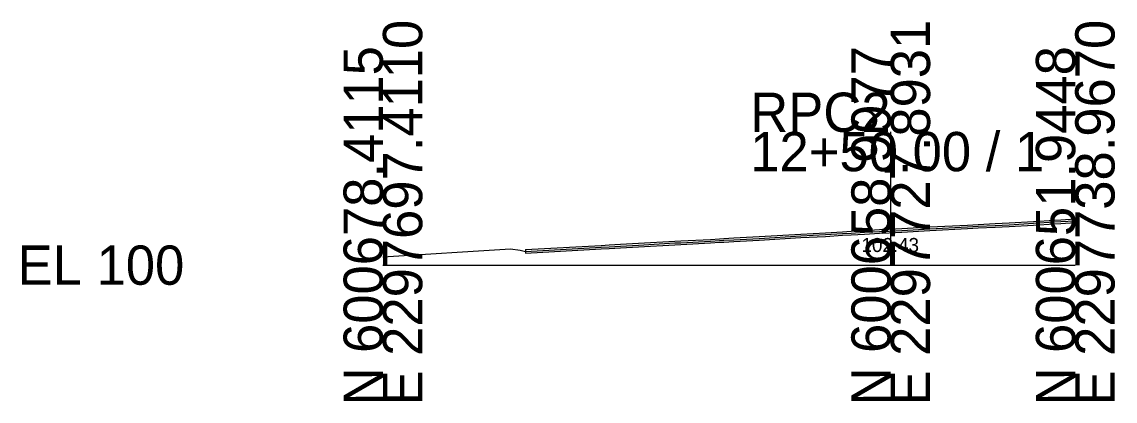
# Model space of a CAD drawing. Extents: x 2124 to 2376, y -10 to 1517.
# Drawn here: x 2124.3 to 2202.1, y 1490.3 to 1517.3 of the extents above; entities that cross this region are included whole.
import ezdxf

# ---------------------------------------------------------------- set-up
doc = ezdxf.new("R2010")
doc.units = 0
for name, color, linetype in [('Exist Cross Section Cell', 7, 'Continuous'), ('Exist XS Center Line Elevation Label', 7, 'Continuous'), ('Exist XS Ground Line', 7, 'Continuous'), ('Prop CMT Pvmt Surface', 7, 'Continuous'), ('Prop CMT Pvmt Surface Overlay', 7, 'Continuous')]:
    doc.layers.add(name, color=color, linetype=linetype)

msp = doc.modelspace()

# ---------------------------------------------------------------- linework, layer by layer
at = {"layer": 'Exist Cross Section Cell'}
for p, q in [((2186.139, 1500), (2186.139, 1509.492)), ((2150, 1500), (2186.139, 1500)), ((2186.139, 1500), (2199.269, 1500))]:
    msp.add_line(p, q, dxfattribs=at)
at = {"layer": 'Exist XS Ground Line'}
msp.add_lwpolyline([(2150, 1500.584), (2159.091, 1501.16), (2159.776, 1501.06), (2160.141, 1500.978), (2165.542, 1501.282), (2166.094, 1501.316), (2166.898, 1501.36), (2168.181, 1501.435), (2170.786, 1501.578), (2171.196, 1501.596), (2173.314, 1501.703), (2173.947, 1501.758), (2174.264, 1501.771), (2174.966, 1501.81), (2176.781, 1501.906), (2179.745, 1502.085), (2181.507, 1502.177), (2182.709, 1502.256), (2183.318, 1502.287), (2184.274, 1502.344), (2185.346, 1502.403), (2186.021, 1502.428), (2186.476, 1502.454), (2186.939, 1502.479), (2188.927, 1502.598), (2191.601, 1502.734), (2192.372, 1502.78), (2193.581, 1502.836), (2194.565, 1502.881), (2196.291, 1502.985), (2197.804, 1503.075), (2198.235, 1503.103), (2199.269, 1503.164)], dxfattribs=at)
at = {"layer": 'Prop CMT Pvmt Surface'}
msp.add_line((2160.141, 1501.103), (2160.141, 1500.853), dxfattribs=at)
for points in [[(2160.141, 1501.103), (2165.542, 1501.407), (2166.094, 1501.441), (2166.898, 1501.485), (2168.181, 1501.56), (2170.786, 1501.703), (2171.196, 1501.721), (2173.314, 1501.828), (2173.947, 1501.883), (2174.264, 1501.896), (2174.966, 1501.935), (2176.781, 1502.031), (2179.745, 1502.21), (2181.507, 1502.302), (2182.709, 1502.381), (2183.318, 1502.412), (2184.274, 1502.469), (2185.346, 1502.528), (2186.021, 1502.553), (2186.476, 1502.579), (2186.939, 1502.604), (2188.927, 1502.723), (2191.601, 1502.859), (2192.372, 1502.905), (2193.581, 1502.961), (2194.565, 1503.006), (2196.291, 1503.11), (2197.804, 1503.2), (2198.235, 1503.228), (2199.269, 1503.289)], [(2160.141, 1500.853), (2165.542, 1501.157), (2166.094, 1501.191), (2166.898, 1501.235), (2168.181, 1501.31), (2170.786, 1501.453), (2171.196, 1501.471), (2173.314, 1501.578), (2173.947, 1501.633), (2174.264, 1501.646), (2174.966, 1501.685), (2176.781, 1501.781), (2179.745, 1501.96), (2181.507, 1502.052), (2182.709, 1502.131), (2183.318, 1502.162), (2184.274, 1502.219), (2185.346, 1502.278), (2186.021, 1502.303), (2186.476, 1502.329), (2186.939, 1502.354), (2188.927, 1502.473), (2191.601, 1502.609), (2192.372, 1502.655), (2193.581, 1502.711), (2194.565, 1502.756), (2196.291, 1502.86), (2197.804, 1502.95), (2198.235, 1502.978), (2199.269, 1503.039)]]:
    msp.add_lwpolyline(points, dxfattribs=at)
at = {"layer": 'Prop CMT Pvmt Surface Overlay'}
for p, q in [((2199.269, 1503.289), (2199.269, 1503.039)), ((2160.141, 1501.103), (2160.141, 1500.853))]:
    msp.add_line(p, q, dxfattribs=at)
for points in [[(2160.141, 1501.103), (2165.542, 1501.407), (2166.094, 1501.441), (2166.898, 1501.485), (2168.181, 1501.56), (2170.786, 1501.703), (2171.196, 1501.721), (2173.314, 1501.828), (2173.947, 1501.883), (2174.264, 1501.896), (2174.966, 1501.935), (2176.781, 1502.031), (2179.745, 1502.21), (2181.507, 1502.302), (2182.709, 1502.381), (2183.318, 1502.412), (2184.274, 1502.469), (2185.346, 1502.528), (2186.021, 1502.553), (2186.476, 1502.579), (2186.939, 1502.604), (2188.927, 1502.723), (2191.601, 1502.859), (2192.372, 1502.905), (2193.581, 1502.961), (2194.565, 1503.006), (2196.291, 1503.11), (2197.804, 1503.2), (2198.235, 1503.228), (2199.269, 1503.289)], [(2160.141, 1500.853), (2165.542, 1501.157), (2166.094, 1501.191), (2166.898, 1501.235), (2168.181, 1501.31), (2170.786, 1501.453), (2171.196, 1501.471), (2173.314, 1501.578), (2173.947, 1501.633), (2174.264, 1501.646), (2174.966, 1501.685), (2176.781, 1501.781), (2179.745, 1501.96), (2181.507, 1502.052), (2182.709, 1502.131), (2183.318, 1502.162), (2184.274, 1502.219), (2185.346, 1502.278), (2186.021, 1502.303), (2186.476, 1502.329), (2186.939, 1502.354), (2188.927, 1502.473), (2191.601, 1502.609), (2192.372, 1502.655), (2193.581, 1502.711), (2194.565, 1502.756), (2196.291, 1502.86), (2197.804, 1502.95), (2198.235, 1502.978), (2199.269, 1503.039)]]:
    msp.add_lwpolyline(points, dxfattribs=at)

# ---------------------------------------------------------------- texts
at = {"layer": 'Exist Cross Section Cell'}
for s, p in [('E 2297697.4110', (2152.8, 1490)), ('E 2297727.8931', (2188.939, 1490)), ('E 2297738.9670', (2202.069, 1490)), ('N 600678.4115', (2150, 1490)), ('N 600658.9977', (2186.139, 1490)), ('N 600651.9448', (2199.269, 1490))]:
    msp.add_text(s, height=2.8, rotation=90, dxfattribs=at).set_placement(p)
for s, p in [('RPC2', (2176.139, 1509.492)), ('12+50.00 / 1', (2176.139, 1506.692)), ('EL 100', (2124, 1498.6))]:
    msp.add_text(s, height=2.8, dxfattribs=at).set_placement(p)
at = {"layer": 'Exist XS Center Line Elevation Label'}
msp.add_text('102.43', height=1, dxfattribs=at).set_placement((2184.061, 1500.935))

doc.saveas('drawing.dxf')
